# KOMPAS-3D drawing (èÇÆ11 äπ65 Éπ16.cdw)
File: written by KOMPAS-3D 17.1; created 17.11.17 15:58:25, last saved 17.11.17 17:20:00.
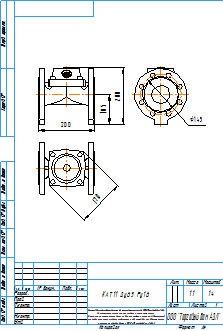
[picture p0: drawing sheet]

Sheet 1: A4, portrait

Title block, sheet 1: name: КАТ11 Ду65 Ру16; material: Сталь 20  ГОСТ 1050-88; mass: 11; sheets: 1; sheet format: A4; stored path: \\adlc.lan\data\АДЛ_ПКД\3D-модели\ADL production\Клапаны КАТ ГРАНРЕГ\КАТ11\KOMPAS 2D\КАТ11 Ду65 Ру16.cdw

Views: Вид 1, Проекционный вид 2, Проекционный вид 3
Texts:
  kka
  adl
  Рама для чертежей
  Лит-Масса-Масштаб
  Материал-Предприятие
  Масштаб
  Изм.
  Лист
  № докум.
  Подп.
  Дата
  Лит.
  Разраб.
  Пров.
  Т.контр.
  Листов
  Внимание! Данный продукт является объектом авторского права ООО «Торговый Дом АДЛ».
  Запрещается изменение, копирование, распространение
  (в том числе путем копирования на другие сайты и ресурсы в Интернете)
  или любое иное использование информации и объектов без предварительного
  согласия правообладателя (ООО «Торговый Дом АДЛ»).
  Н.контр.
  Утв.
  ООО "Торговый дом АДЛ"
  Изменение
  Номер документа
  Подпись
  Обозначение документа
  Наименование изделия
  Масса изделия по ГОСТ 2.109-73
  Порядковый номер листа
  Общее количество листов в документе
  Характер работы, выполненной лицом, подписавшим документ
  Наименование или индекс предприятия, выпускающего документ
  Инв. № подл.
  Подп. и дата
  Взам. инв. №
  Инв. № дубл.
  Инвентарный номер подлинника по ГОСТ 2.501-68
  Подпись принявшего подлинник в отдел технической документации
  Инвентарный номер подлинника, взамен которого выпущен данный подлинник
  Инвентарный номер дубликата по ГОСТ 2.502-68
  Подпись принявшего дубликат в отдел технической документации
  Справ. №
  Перв. примен.
  Обозначение документа, взамен или на основании которого выпущен данный документ
  Обозначение документа, в котором впервые записан данный документ
  Подпись лица, копировавшего чертеж
  Обозначение формата листа
  !Рама для чертежа
Dimensions and other numbers on the sheet: 200; 105; 145; 170; 1:4; 1; 11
